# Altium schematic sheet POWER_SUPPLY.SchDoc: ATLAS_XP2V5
size 558 x 431 mm; Organization: IMP Automatika d.o.o.; Revision: V5
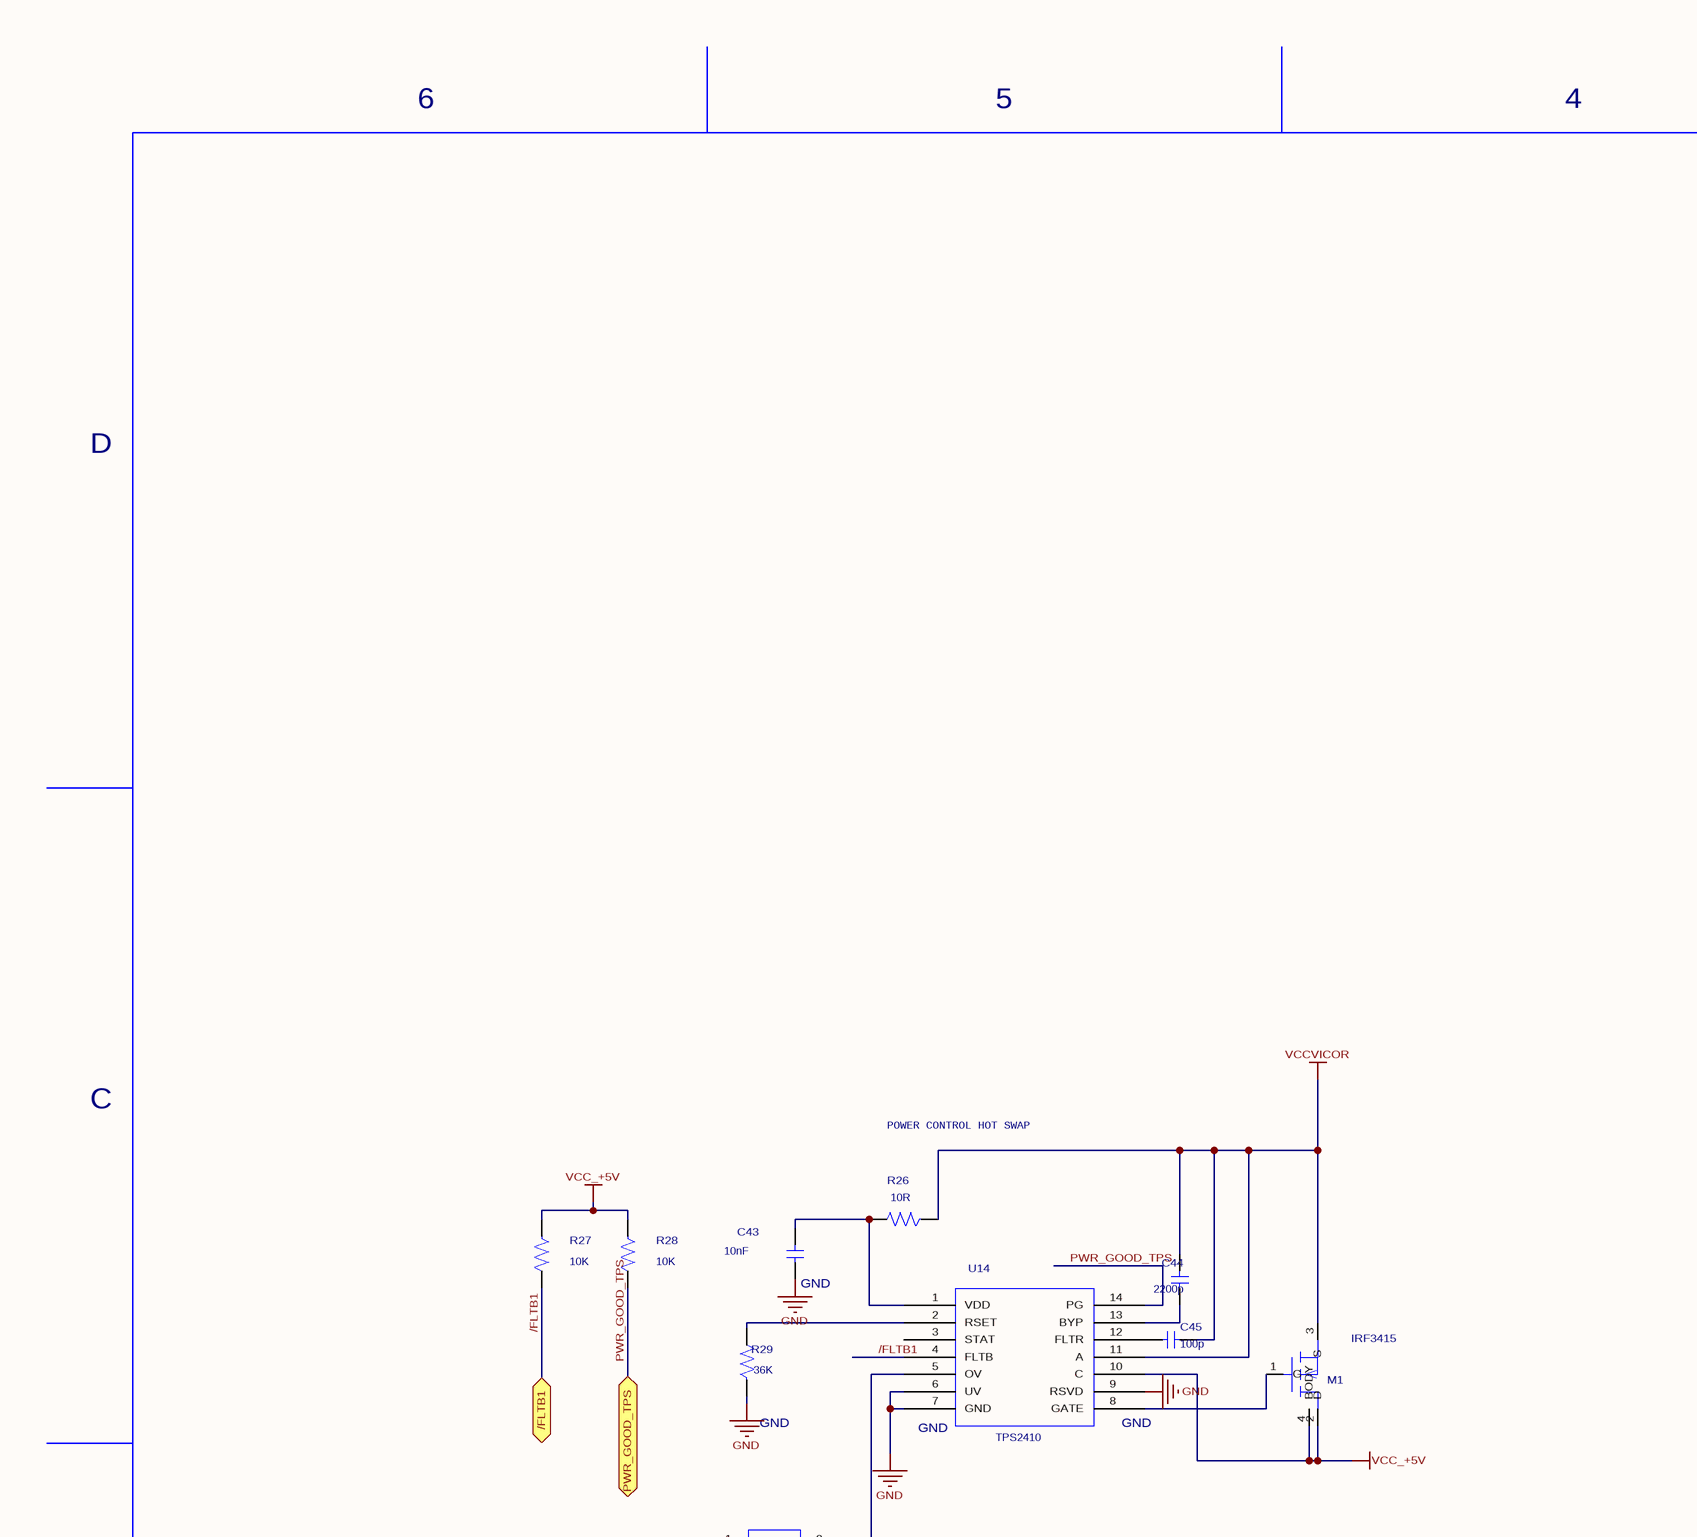
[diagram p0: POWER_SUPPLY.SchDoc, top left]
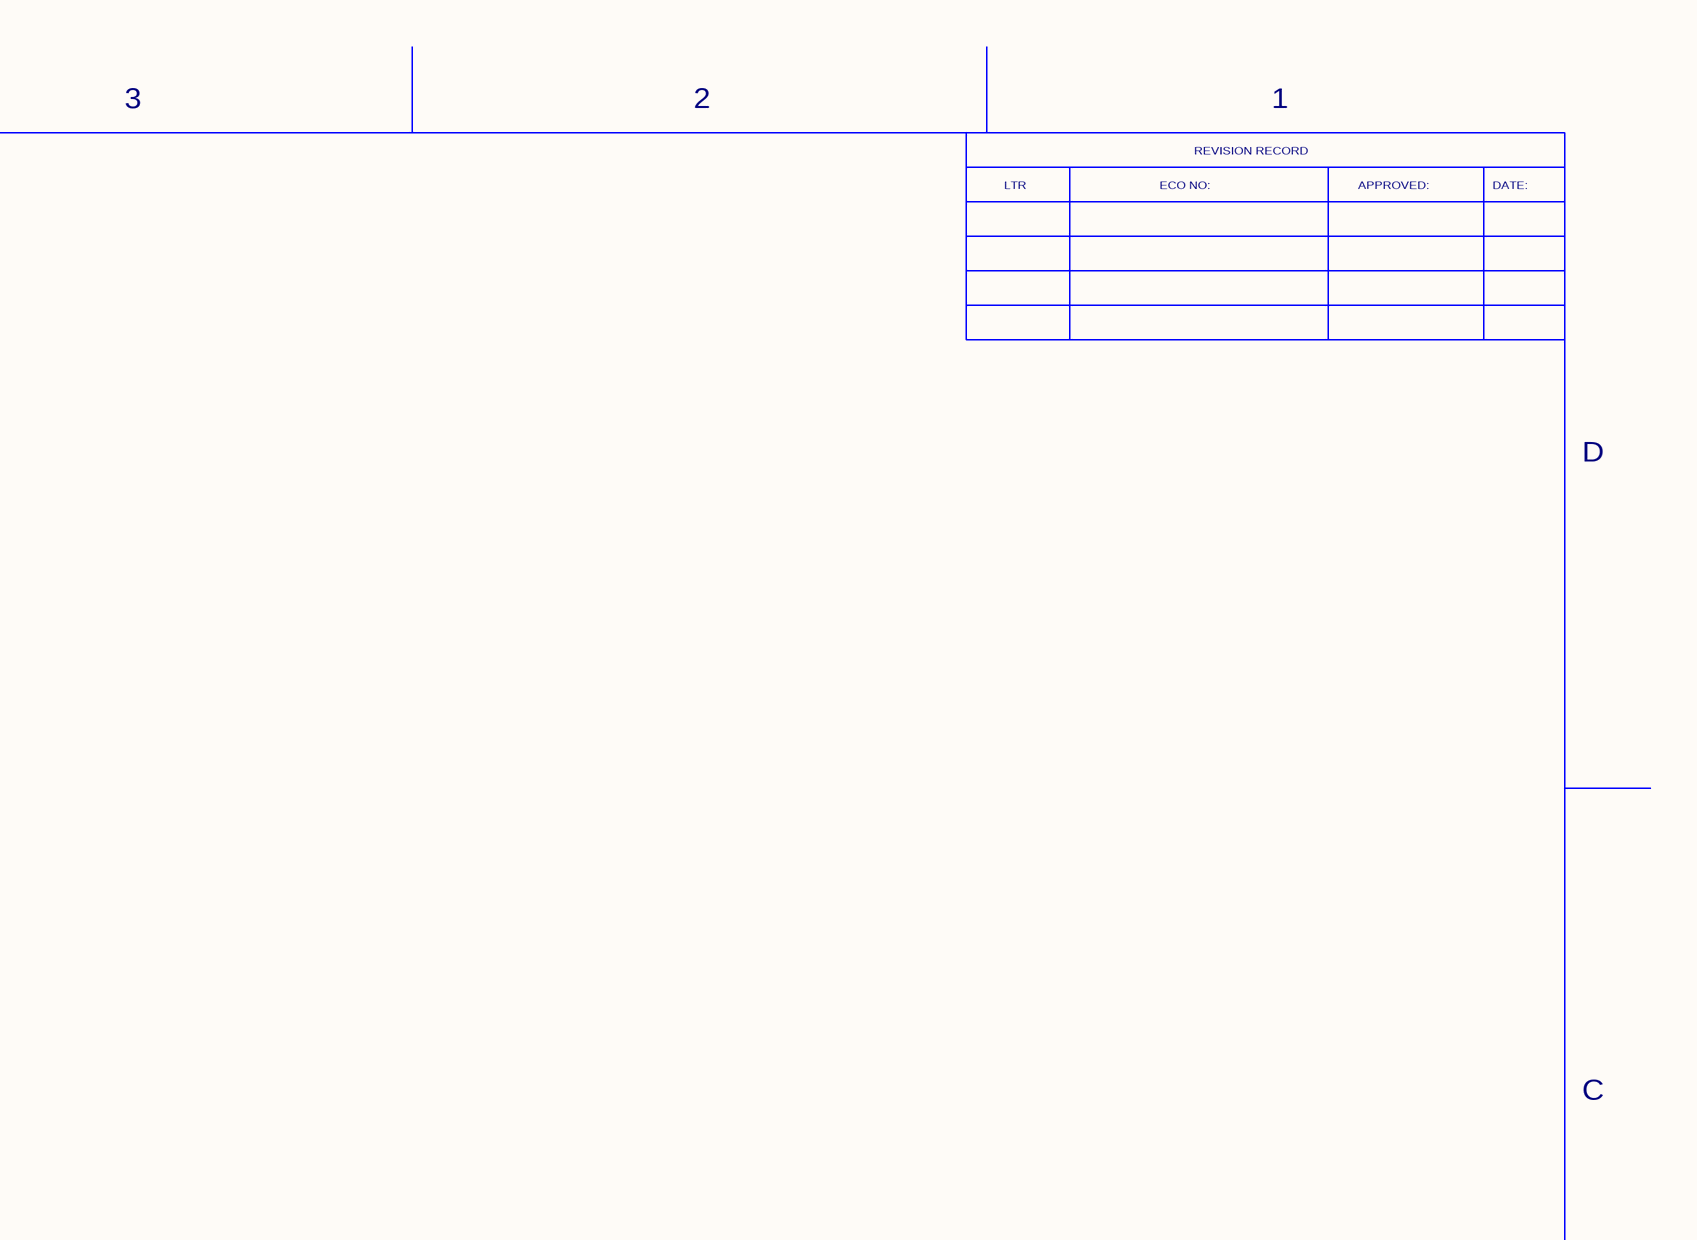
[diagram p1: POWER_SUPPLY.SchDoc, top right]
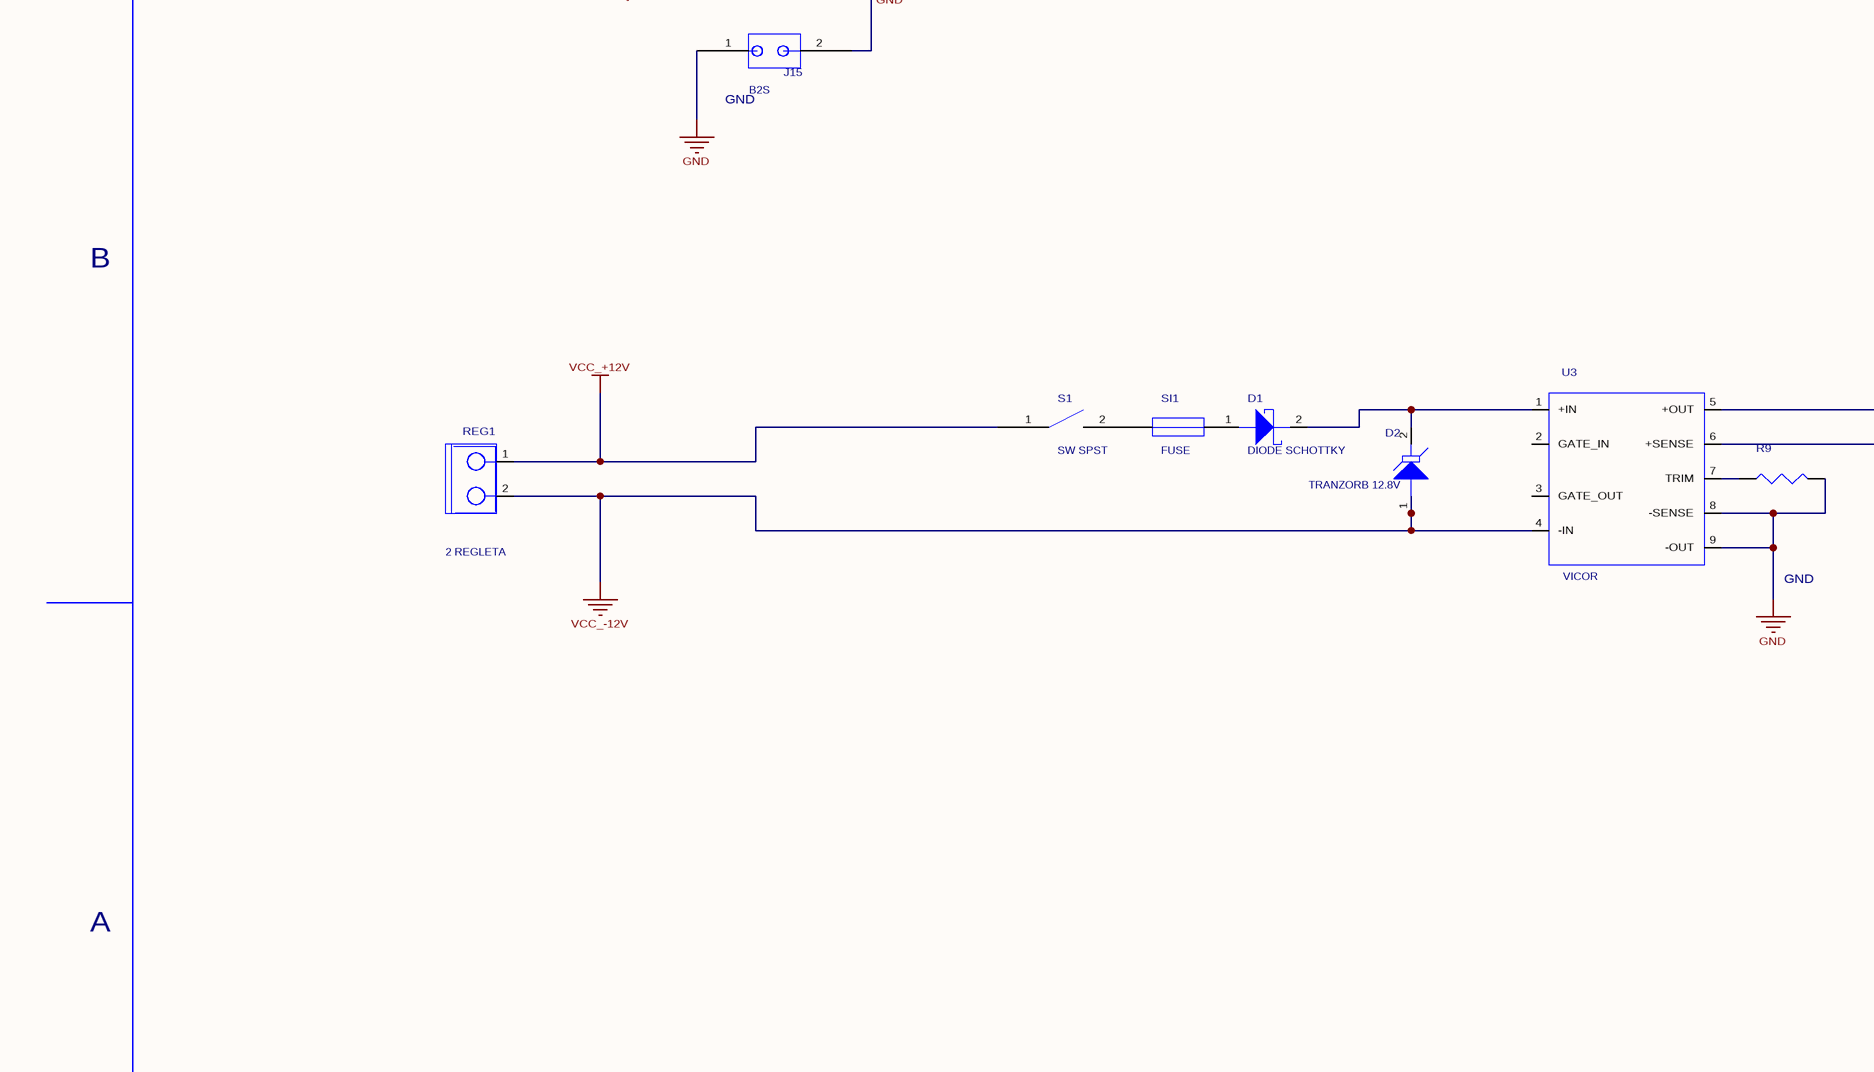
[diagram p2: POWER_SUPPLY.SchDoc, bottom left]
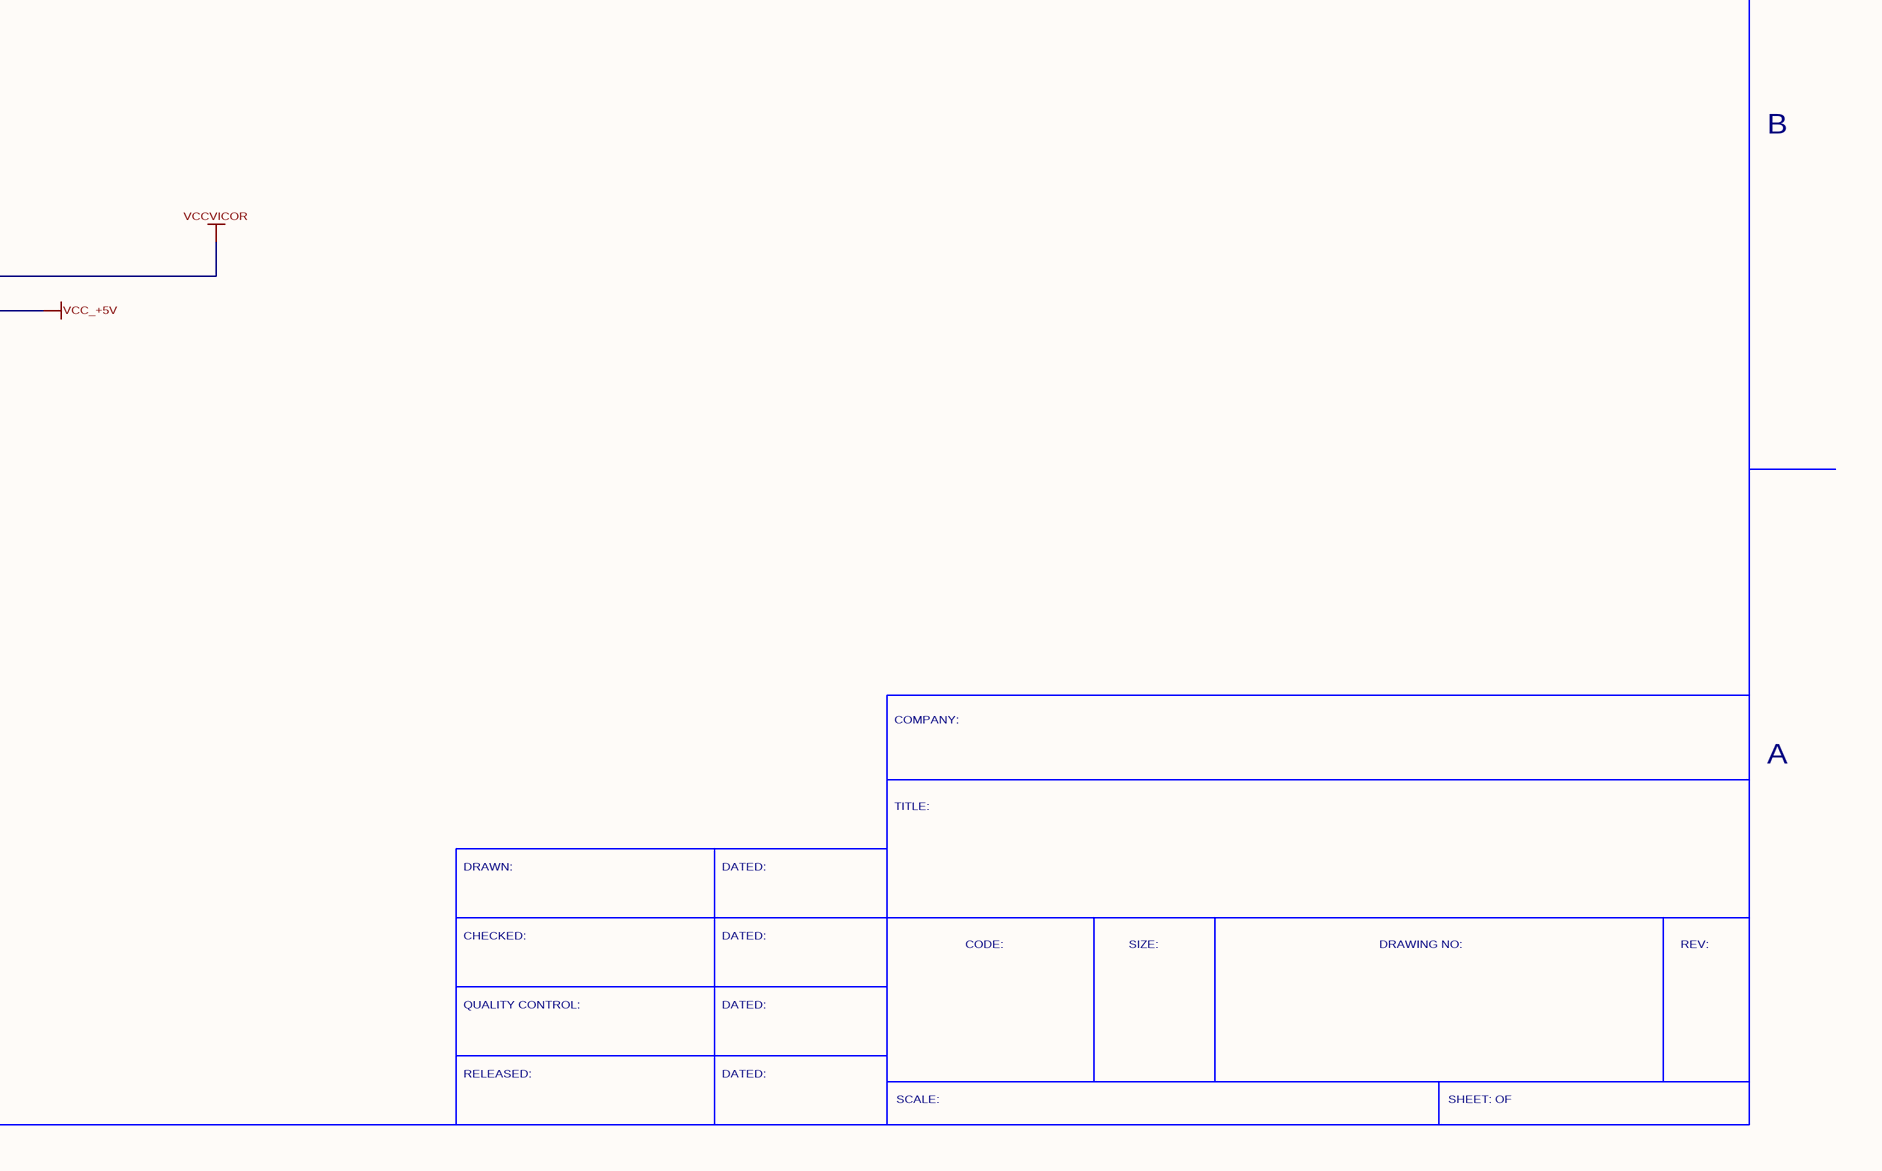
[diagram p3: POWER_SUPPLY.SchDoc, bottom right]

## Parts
C43  value 10nF  [SM/C_0805]  (hidden comment: C_3)
C44  value 2200p  [SM/C_0805]  (hidden comment: C_3)
C45  value 100p  [SM/C_0805]  (hidden comment: C_3)
D1  value DIODE SCHOTTKY  [SM/DO214AB_21]  (hidden comment: DIODE_SCHOTTKY_0)
D2  value TRANZORB 12.8V  [SM/DO214AC_21]  (hidden comment: TRANZORB_0)
J15  value B2S  [JUMPER_100]  (hidden comment: B2S_0)
M1  value IRF3415  [IRF3415_PADS_REV1]  (hidden comment: IRF3415_BODY)
R9  RESISTOR  [SM/R_1206]  (value not drawn)
R26  value 10R  [SM/R_1206]  (hidden comment: R)
R27  value 10K  [SM/R_1206]  (hidden comment: R)
R28  value 10K  [SM/R_1206]  (hidden comment: R)
R29  value 36K  [SM/R_1206]  (hidden comment: R)
REG1  value 2 REGLETA  [REG2_REV8]  (hidden comment: 8_REGLETA_4)
S1  value SW SPST  [SW12V_REV2]  (hidden comment: SW_SPST_0)
SI1  FUSE  [FUSEHOLDER3]
U3  VICOR  [VIKOR1]
U14  value TPS2410  [PDSO-G14_REV7]  (hidden comment: TPS2410_1)

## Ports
/FLTB1 (bidir), PWR_GOOD_TPS (bidir)

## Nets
GND: C43.1 J15.1 R9.2 R29.1 U3.8(-SENSE) U3.9(-OUT) U14.6(UV) U14.7(GND) U14.9(RSVD)
VCC_+5V: M1.2(D) M1.4(BODY) R27.1 R28.1 U3.6(+SENSE) U14.10(C)
VCC_+12V: REG1.1 S1.1(COMMON)
VCC_-12V: D2.1(ANODE) REG1.2 U3.4(-IN)
VCCVICOR: C44.2 C45.1 M1.3(S) R26.1 U3.5(+OUT) U14.11(A)
/FLTB1: R27.2 U14.4(FLTB) ; port /FLTB1
PWR_GOOD_TPS: R28.2 U14.14(PG) ; port PWR_GOOD_TPS
NetC43_2: C43.2 R26.2 U14.1(VDD)
NetC44_1: C44.1 U14.13(BYP)
NetC45_2: C45.2 U14.12(FLTR)
NetD1_1: D1.1(ANODE) SI1.2
NetD1_2: D1.2(CATHODE) D2.2(CATHODE) U3.1(+IN)
NetJ15_2: J15.2 U14.5(OV)
NetM1_1: M1.1(G) U14.8(GATE)
NetR9_1: R9.1 U3.7(TRIM)
NetR29_2: R29.2 U14.2(RSET)
NetS1_2: S1.2(NO) SI1.1

Not connected (* = marked no-connect by the designer): U3 2(GATE_IN) 3(GATE_OUT); U14 3(STAT)

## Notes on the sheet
- 6
- 5
- 4
- 3
- 2
- 1
- LTR
- ECO NO:
- REVISION RECORD
- APPROVED:
- DATE:
- D
- C
- POWER CONTROL HOT SWAP
- (near C43) GND
- (near R29) GND
- (near U14) GND
- (near J15) GND
- B
- GND
- COMPANY:
- A
- TITLE:
- DRAWN:
- DATED:
- CHECKED:
- CODE:
- SIZE:
- DRAWING NO:
- REV:
- QUALITY CONTROL:
- RELEASED:
- SCALE:
- SHEET: OF

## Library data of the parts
C43 = C_3: COMPSIDE: TOP; COMPLOC: [-4300.000,200.000]; COMPROT: 0; COMPFIXED: NO; COMPHEIGHT: 0.000; Source_Path: C:\ORCAD\ORCAD_10.0\TOOLS\CAPTURE\LIBRARY\PSPICE\ANALOG.OLB; DIST: FLAT; PSpiceTemplate: C^@REFDES %1 %2 ?TOLERANCE¦C^@REFDES¦ @VALUE ?IC/IC=@IC/ ?TOLERANCE¦\n.model C^@REFDES CAP C=1 DEV=@TOLERANCE%¦; VOLTAGE: CMAX; CURRENT: CIMAX; KNEE: CBMAX; SLOPE: CSMAX; MAX_TEMP: CTMAX
C44 = C_3: COMPSIDE: TOP; COMPLOC: [-3400.000,200.000]; COMPROT: 0; COMPFIXED: NO; COMPHEIGHT: 0.000; Source_Path: C:\ORCAD\ORCAD_10.0\TOOLS\CAPTURE\LIBRARY\PSPICE\ANALOG.OLB; DIST: FLAT; PSpiceTemplate: C^@REFDES %1 %2 ?TOLERANCE¦C^@REFDES¦ @VALUE ?IC/IC=@IC/ ?TOLERANCE¦\n.model C^@REFDES CAP C=1 DEV=@TOLERANCE%¦; VOLTAGE: CMAX; CURRENT: CIMAX; KNEE: CBMAX; SLOPE: CSMAX; MAX_TEMP: CTMAX
C45 = C_3: COMPHEIGHT: 0.000; MEMORY: NO; COMPGROUP: 0; COMPLOC: [-3700.000,200.000]; COMPSIDE: TOP; Source_Path: C:\ORCAD\ORCAD_10.0\TOOLS\CAPTURE\LIBRARY\PSPICE\ANALOG.OLB; DIST: FLAT; PSpiceTemplate: C^@REFDES %1 %2 ?TOLERANCE¦C^@REFDES¦ @VALUE ?IC/IC=@IC/ ?TOLERANCE¦\n.model C^@REFDES CAP C=1 DEV=@TOLERANCE%¦; VOLTAGE: CMAX; CURRENT: CIMAX; KNEE: CBMAX; SLOPE: CSMAX; MAX_TEMP: CTMAX
D1 = DIODE_SCHOTTKY_0: Source_Path: C:\CADENCE\PSD_15.1\TOOLS\ATLAS_ITA\ATLAS_ITA.DSN
D2 = TRANZORB_0: Source_Path: C:\CADENCE\PSD_15.1\TOOLS\ATLAS_ITA\ATLAS_ITA.DSN
J15 = B2S_0: Source_Path: C:\CADENCE\PSD_15.1\TOOLS\ATLAS_ITA\ATLAS_ITA.DSN
M1 = IRF3415_BODY: COMPSIDE: TOP; COMPLOC: [-1200.000,2000.000]; COMPROT: 0; COMPFIXED: NO; COMPHEIGHT: 0.000; Source_Path: C:\CADENCE\PSD_15.1\TOOLS\ATLAS_ITA\ATLAS_ITA.DSN; PSpiceTemplate: M^@REFDES %d %g %s %s @MODEL
R9 = RESISTOR: Source_Path: C:\PROGRAM FILES\ORCAD\CAPTURE\LIBRARY\DISCRETE.OLB
R26 = R: COMPSIDE: TOP; COMPLOC: [-2400.000,2400.000]; COMPROT: 0; COMPFIXED: NO; COMPHEIGHT: 0.000; Source_Path: C:\ORCAD\ORCAD_10.0\TOOLS\CAPTURE\LIBRARY\PSPICE\ANALOG.OLB; DIST: FLAT; PSpiceTemplate: R^@REFDES %1 %2 ?TOLERANCE¦R^@REFDES¦ @VALUE  ?TOLERANCE¦\n.model R^@REFDES RES R=1 DEV=@TOLERANCE%¦; VOLTAGE: RVMAX; SLOPE: RSMAX; MAX_TEMP: RTMAX; POWER: RMAX
R27 R28 = R: Source_Path: C:\ORCAD\ORCAD_10.0\TOOLS\CAPTURE\LIBRARY\PSPICE\ANALOG.OLB; DIST: FLAT; PSpiceTemplate: R^@REFDES %1 %2 ?TOLERANCE¦R^@REFDES¦ @VALUE  ?TOLERANCE¦\n.model R^@REFDES RES R=1 DEV=@TOLERANCE%¦; VOLTAGE: RVMAX; SLOPE: RSMAX; MAX_TEMP: RTMAX; POWER: RMAX
R29 = R: COMPHEIGHT: 0.000; MEMORY: NO; COMPGROUP: 0; COMPLOC: [-2400.000,2400.000]; COMPSIDE: TOP; Source_Path: C:\ORCAD\ORCAD_10.0\TOOLS\CAPTURE\LIBRARY\PSPICE\ANALOG.OLB; DIST: FLAT; PSpiceTemplate: R^@REFDES %1 %2 ?TOLERANCE¦R^@REFDES¦ @VALUE  ?TOLERANCE¦\n.model R^@REFDES RES R=1 DEV=@TOLERANCE%¦; VOLTAGE: RVMAX; SLOPE: RSMAX; MAX_TEMP: RTMAX; POWER: RMAX
REG1 = 8_REGLETA_4: Source_Path: E:\MILOS\PROJECTS\ATLAS_XP\ATLAS_XP.DSN; SDTSourceLibName: C:\WINDOWS\TEMP\ATP_00.LIB
S1 = SW_SPST_0: Source_Path: C:\CADENCE\PSD_15.1\TOOLS\ATLAS_ITA\ATLAS_ITA.DSN
SI1 = FUSE: Source_Path: C:\CADENCE\PSD_15.1\TOOLS\CAPTURE\LIBRARY\IEC\DEVICE.OLB
U3 = VICOR: Source_Path: C:\DOCUMENTS AND SETTINGS\RAYVOJ HARDWAREA\DESKTOP\MILOSH.OLB
U14 = TPS2410_1: FPLIST: DIP.100B/14/W.300/L.800; COMPSIDE: TOP; COMPLOC: [-700.000,900.000]; COMPROT: 0; COMPFIXED: NO; COMPHEIGHT: 0.000; Source_Path: C:\ORCAD\PROJECTS\PUPINATPPCB.DSN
